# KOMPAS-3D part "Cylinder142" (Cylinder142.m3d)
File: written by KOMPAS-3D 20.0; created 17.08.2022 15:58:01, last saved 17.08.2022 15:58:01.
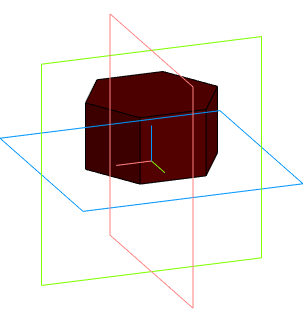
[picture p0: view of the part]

Document properties: Автор: artemsv220@gmail.com; Полное имя файла: \\192.168.2.25\новая общая папка\Медиа\Светильники\Кашпо\Кашпо и вазоны\DWG\Cylinder142.m3d

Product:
- Part/product: Cylinder142

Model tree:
1. Операция без истории:1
